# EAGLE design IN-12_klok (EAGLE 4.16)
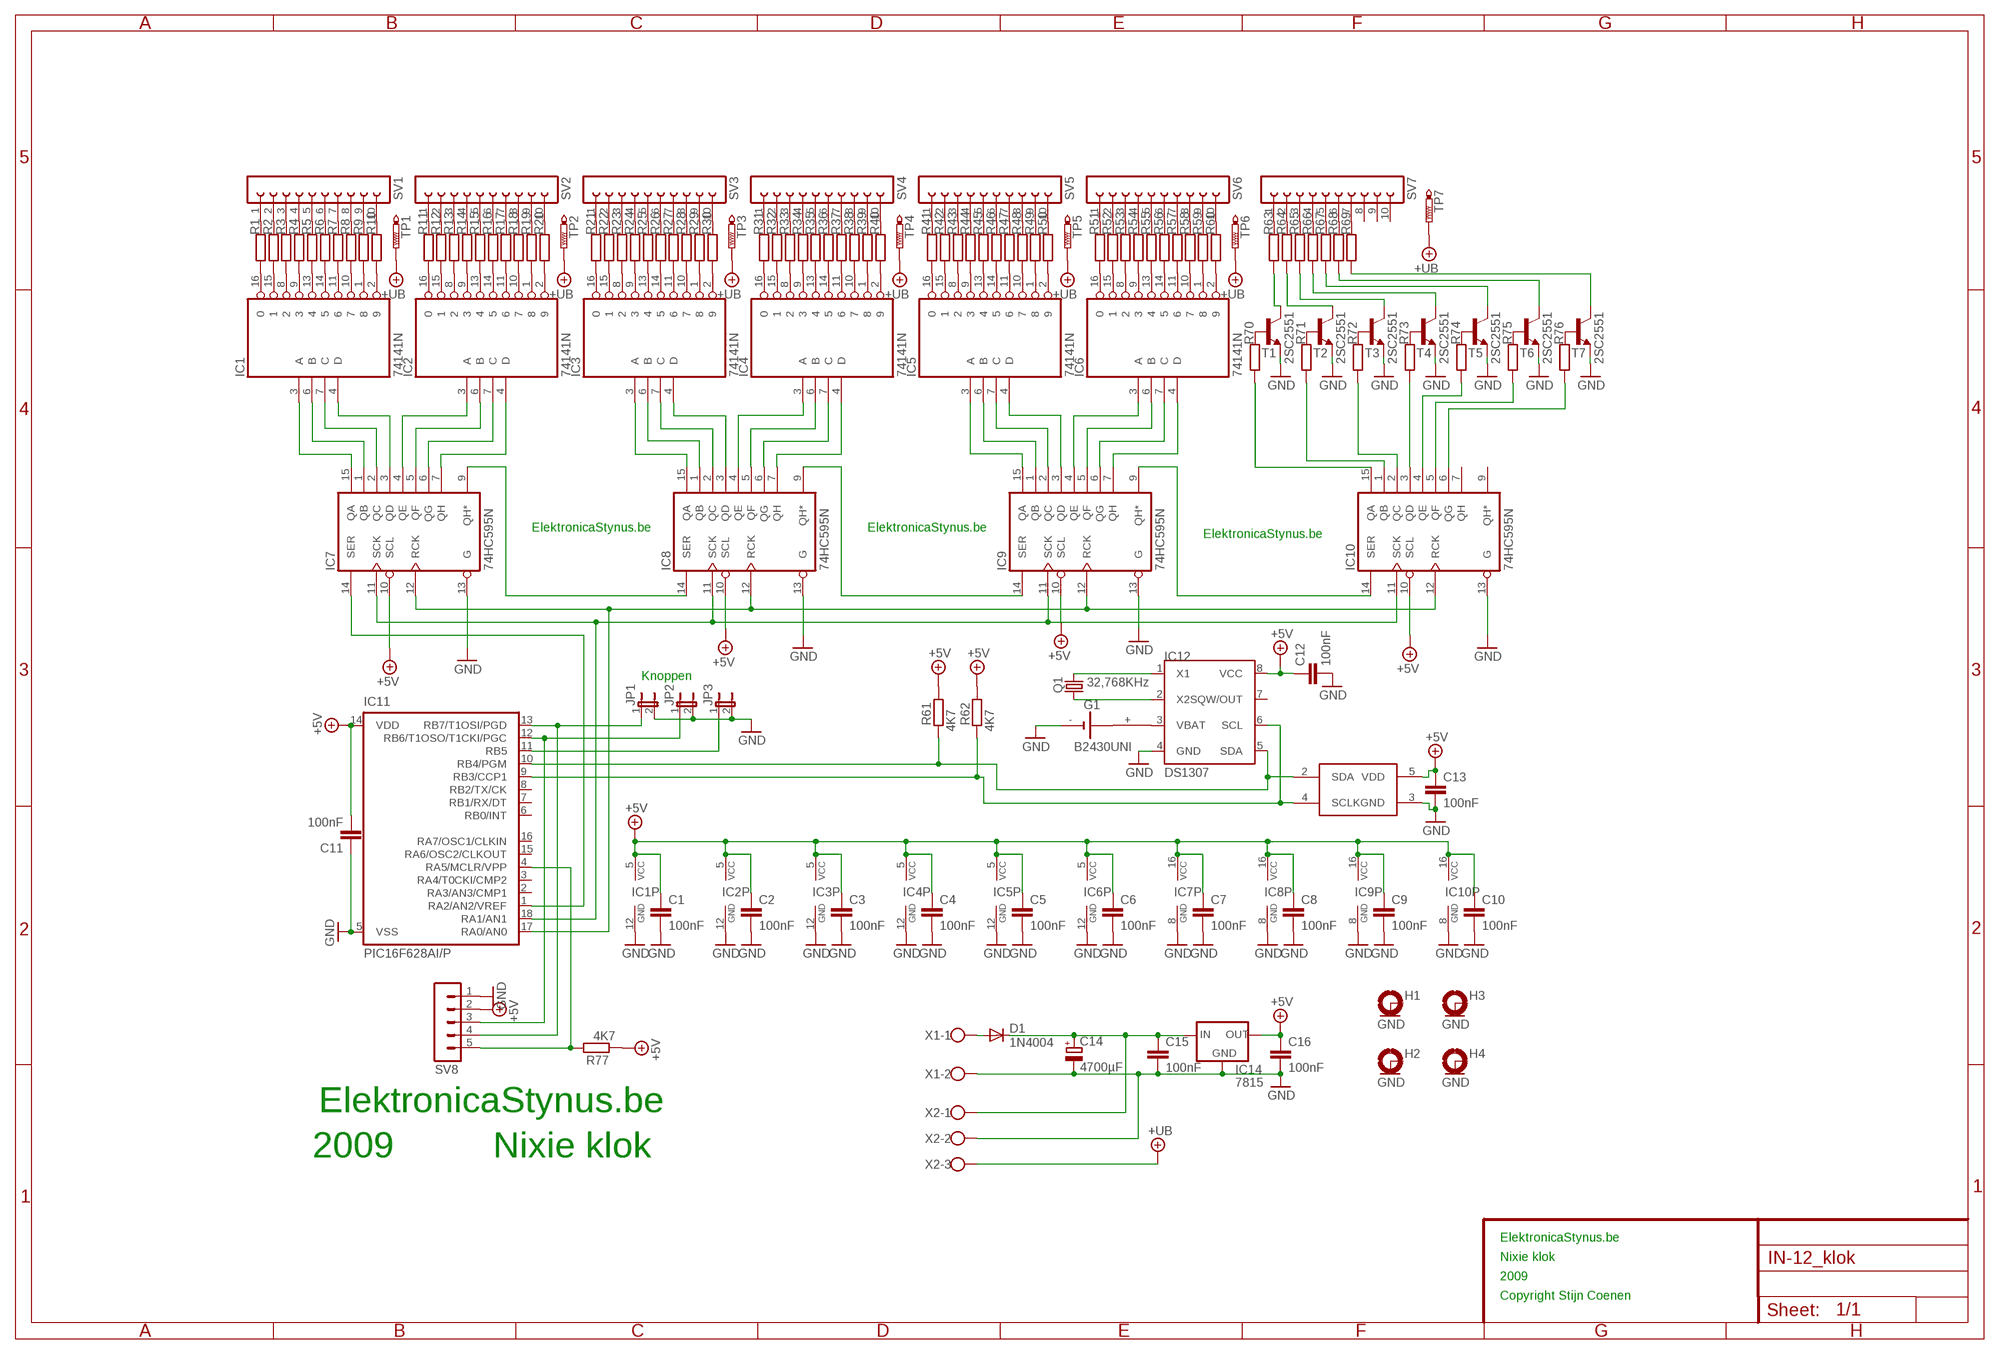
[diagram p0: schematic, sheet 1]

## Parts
C1  100nF  C-EU050-025X075  [C050-025X075]
C2  100nF  C-EU050-025X075  [C050-025X075]
C3  100nF  C-EU050-025X075  [C050-025X075]
C4  100nF  C-EU050-025X075  [C050-025X075]
C5  100nF  C-EU050-025X075  [C050-025X075]
C6  100nF  C-EU050-025X075  [C050-025X075]
C7  100nF  C-EU050-025X075  [C050-025X075]
C8  100nF  C-EU050-025X075  [C050-025X075]
C9  100nF  C-EU050-025X075  [C050-025X075]
C10  100nF  C-EU050-025X075  [C050-025X075]
C11  100nF  C-EU050-025X075  [C050-025X075]
C12  100nF  C-EU050-025X075  [C050-025X075]
C13  100nF  C-EU050-025X075  [C050-025X075]
C14  4700µF  CPOL-EUE7.5-18  [E7,5-18]
C15  100nF  C-EU050-025X075  [C050-025X075]
C16  100nF  C-EU050-025X075  [C050-025X075]
D1  1N4004  [DO41-10]
G1  B2430UNI  [B2430UNI]
H1  MOUNT-PAD-ROUND3.0  [3,0-PAD]
H2  MOUNT-PAD-ROUND3.0  [3,0-PAD]
H3  MOUNT-PAD-ROUND3.0  [3,0-PAD]
H4  MOUNT-PAD-ROUND3.0  [3,0-PAD]
IC1  74141N  [DIL16]
IC2  74141N  [DIL16]
IC3  74141N  [DIL16]
IC4  74141N  [DIL16]
IC5  74141N  [DIL16]
IC6  74141N  [DIL16]
IC7  74HC595N  [DIL16]
IC8  74HC595N  [DIL16]
IC9  74HC595N  [DIL16]
IC10  74HC595N  [DIL16]
IC11  PIC16F628AI/P  [DIL18]
IC12  DS1307  [DIL8]
IC13  TC74  [CB360]
IC14  7815  78XXS  [78XXS]
JP1  JP1E  [JP1]
JP2  JP1E  [JP1]
JP3  JP1E  [JP1]
Q1  32,768KHz  CRYSTALTC38H  [TC38H]
R1  R-EU_0204/7  [0204/7]
R2  R-EU_0204/7  [0204/7]
R3  R-EU_0204/7  [0204/7]
R4  R-EU_0204/7  [0204/7]
R5  R-EU_0204/7  [0204/7]
R6  R-EU_0204/7  [0204/7]
R7  R-EU_0204/7  [0204/7]
R8  R-EU_0204/7  [0204/7]
R9  R-EU_0204/7  [0204/7]
R10  R-EU_0204/7  [0204/7]
R11  R-EU_0204/7  [0204/7]
R12  R-EU_0204/7  [0204/7]
R13  R-EU_0204/7  [0204/7]
R14  R-EU_0204/7  [0204/7]
R15  R-EU_0204/7  [0204/7]
R16  R-EU_0204/7  [0204/7]
R17  R-EU_0204/7  [0204/7]
R18  R-EU_0204/7  [0204/7]
R19  R-EU_0204/7  [0204/7]
R20  R-EU_0204/7  [0204/7]
R21  R-EU_0204/7  [0204/7]
R22  R-EU_0204/7  [0204/7]
R23  R-EU_0204/7  [0204/7]
R24  R-EU_0204/7  [0204/7]
R25  R-EU_0204/7  [0204/7]
R26  R-EU_0204/7  [0204/7]
R27  R-EU_0204/7  [0204/7]
R28  R-EU_0204/7  [0204/7]
R29  R-EU_0204/7  [0204/7]
R30  R-EU_0204/7  [0204/7]
R31  R-EU_0204/7  [0204/7]
R32  R-EU_0204/7  [0204/7]
R33  R-EU_0204/7  [0204/7]
R34  R-EU_0204/7  [0204/7]
R35  R-EU_0204/7  [0204/7]
R36  R-EU_0204/7  [0204/7]
R37  R-EU_0204/7  [0204/7]
R38  R-EU_0204/7  [0204/7]
R39  R-EU_0204/7  [0204/7]
R40  R-EU_0204/7  [0204/7]
R41  R-EU_0204/7  [0204/7]
R42  R-EU_0204/7  [0204/7]
R43  R-EU_0204/7  [0204/7]
R44  R-EU_0204/7  [0204/7]
R45  R-EU_0204/7  [0204/7]
R46  R-EU_0204/7  [0204/7]
R47  R-EU_0204/7  [0204/7]
R48  R-EU_0204/7  [0204/7]
R49  R-EU_0204/7  [0204/7]
R50  R-EU_0204/7  [0204/7]
R51  R-EU_0204/7  [0204/7]
R52  R-EU_0204/7  [0204/7]
R53  R-EU_0204/7  [0204/7]
R54  R-EU_0204/7  [0204/7]
R55  R-EU_0204/7  [0204/7]
R56  R-EU_0204/7  [0204/7]
R57  R-EU_0204/7  [0204/7]
R58  R-EU_0204/7  [0204/7]
R59  R-EU_0204/7  [0204/7]
R60  R-EU_0204/7  [0204/7]
R61  4K7  R-EU_0204/7  [0204/7]
R62  4K7  R-EU_0204/7  [0204/7]
R63  R-EU_0204/7  [0204/7]
R64  R-EU_0204/7  [0204/7]
R65  R-EU_0204/7  [0204/7]
R66  R-EU_0204/7  [0204/7]
R67  R-EU_0204/7  [0204/7]
R68  R-EU_0204/7  [0204/7]
R69  R-EU_0204/7  [0204/7]
R70  R-EU_0204/7  [0204/7]
R71  R-EU_0204/7  [0204/7]
R72  R-EU_0204/7  [0204/7]
R73  R-EU_0204/7  [0204/7]
R74  R-EU_0204/7  [0204/7]
R75  R-EU_0204/7  [0204/7]
R76  R-EU_0204/7  [0204/7]
R77  4K7  R-EU_0204/7  [0204/7]
SV1  FE10-1  [FE10]
SV2  FE10-1  [FE10]
SV3  FE10-1  [FE10]
SV4  FE10-1  [FE10]
SV5  FE10-1  [FE10]
SV6  FE10-1  [FE10]
SV7  FE10-1  [FE10]
SV8  MA05-1  [MA05-1]
T1  2SC2551  [TO92-BCE]
T2  2SC2551  [TO92-BCE]
T3  2SC2551  [TO92-BCE]
T4  2SC2551  [TO92-BCE]
T5  2SC2551  [TO92-BCE]
T6  2SC2551  [TO92-BCE]
T7  2SC2551  [TO92-BCE]
TP1  PTR1PAD1-13Y  [P1-13Y]
TP2  PTR1PAD1-13Y  [P1-13Y]
TP3  PTR1PAD1-13Y  [P1-13Y]
TP4  PTR1PAD1-13Y  [P1-13Y]
TP5  PTR1PAD1-13Y  [P1-13Y]
TP6  PTR1PAD1-13Y  [P1-13Y]
TP7  PTR1PAD1-13Y  [P1-13Y]
X1  W237-02P  [W237-132]
X2  W237-3E  [W237-3E]

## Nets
+5V: C1.1 C2.1 C3.1 C4.1 C5.1 C6.1 C7.1 C8.1 C9.1 C10.1 C11.2 C12.1 C13.1 C16.1 IC1.5(VCC) IC2.5(VCC) IC3.5(VCC) IC4.5(VCC) IC5.5(VCC) IC6.5(VCC) IC7.10(SCL) IC7.16(VCC) IC8.10(SCL) IC8.16(VCC) IC9.10(SCL) IC9.16(VCC) IC10.10(SCL) IC10.16(VCC) IC11.14(VDD) IC12.8(VCC) IC13.5(VDD) IC14.OUT R61.2 R62.2 R77.1 SV8.2
+UB: TP1.1(TP) TP2.1(TP) TP3.1(TP) TP4.1(TP) TP5.1(TP) TP6.1(TP) TP7.1(TP) X2.3
GND: C1.2 C2.2 C3.2 C4.2 C5.2 C6.2 C7.2 C8.2 C9.2 C10.2 C11.1 C12.2 C13.2 C14.- C15.2 C16.2 G1.- H1.B3,0(MOUNT) H2.B3,0(MOUNT) H3.B3,0(MOUNT) H4.B3,0(MOUNT) IC1.12(GND) IC2.12(GND) IC3.12(GND) IC4.12(GND) IC5.12(GND) IC6.12(GND) IC7.8(GND) IC7.13(G) IC8.8(GND) IC8.13(G) IC9.8(GND) IC9.13(G) IC10.8(GND) IC10.13(G) IC11.5(VSS) IC12.4(GND) IC13.3(GND) IC14.GND JP1.2 JP2.2 JP3.2 SV8.1 T1.E T2.E T3.E T4.E T5.E T6.E T7.E X1.2 X2.2
N$1: IC1.3(A) IC7.15(QA)
N$2: IC1.6(B) IC7.1(QB)
N$3: IC1.7(C) IC7.2(QC)
N$4: IC1.4(D) IC7.3(QD)
N$5: IC2.3(A) IC7.4(QE)
N$6: IC2.6(B) IC7.5(QF)
N$7: IC2.7(C) IC7.6(QG)
N$8: IC2.4(D) IC7.7(QH)
N$9: IC3.4(D) IC8.3(QD)
N$10: IC3.7(C) IC8.2(QC)
N$11: IC3.6(B) IC8.1(QB)
N$12: IC3.3(A) IC8.15(QA)
N$13: IC4.3(A) IC8.4(QE)
N$14: IC4.6(B) IC8.5(QF)
N$15: IC4.7(C) IC8.6(QG)
N$16: IC4.4(D) IC8.7(QH)
N$17: IC5.4(D) IC9.3(QD)
N$18: IC5.7(C) IC9.2(QC)
N$19: IC5.6(B) IC9.1(QB)
N$20: IC5.3(A) IC9.15(QA)
N$21: IC6.3(A) IC9.4(QE)
N$22: IC6.6(B) IC9.5(QF)
N$23: IC6.7(C) IC9.6(QG)
N$24: IC6.4(D) IC9.7(QH)
N$25: IC7.11(SCK) IC8.11(SCK) IC9.11(SCK) IC10.11(SCK) IC11.18(RA1/AN1)
N$26: IC7.12(RCK) IC8.12(RCK) IC9.12(RCK) IC10.12(RCK) IC11.17(RA0/AN0)
N$27: IC7.14(SER) IC11.1(RA2/AN2/VREF)
N$28: IC7.9(QH*) IC8.14(SER)
N$29: IC8.9(QH*) IC9.14(SER)
N$30: IC9.9(QH*) IC10.14(SER)
N$31: IC1.16 R1.1
N$32: IC1.15 R2.1
N$33: IC1.8 R3.1
N$34: IC1.9 R4.1
N$35: IC1.13 R5.1
N$36: IC1.14 R6.1
N$37: IC1.11 R7.1
N$38: IC1.10 R8.1
N$39: IC1.1 R9.1
N$40: IC1.2 R10.1
N$41: IC2.16 R11.1
N$42: IC2.15 R12.1
N$43: IC2.8 R13.1
N$44: IC2.9 R14.1
N$45: IC2.13 R15.1
N$46: IC2.14 R16.1
N$47: IC2.11 R17.1
N$48: IC2.10 R18.1
N$49: IC2.1 R19.1
N$50: IC2.2 R20.1
N$51: IC3.16 R21.1
N$52: IC3.15 R22.1
N$53: IC3.8 R23.1
N$54: IC3.9 R24.1
N$55: IC3.13 R25.1
N$56: IC3.14 R26.1
N$57: IC3.11 R27.1
N$58: IC3.10 R28.1
N$59: IC3.1 R29.1
N$60: IC3.2 R30.1
N$61: IC4.16 R31.1
N$62: IC4.15 R32.1
N$63: IC4.8 R33.1
N$64: IC4.9 R34.1
N$65: IC4.13 R35.1
N$66: IC4.14 R36.1
N$67: IC4.11 R37.1
N$68: IC4.10 R38.1
N$69: IC4.1 R39.1
N$70: IC4.2 R40.1
N$71: IC5.16 R41.1
N$72: IC5.15 R42.1
N$73: IC5.8 R43.1
N$74: IC5.9 R44.1
N$75: IC5.13 R45.1
N$76: IC5.14 R46.1
N$77: IC5.11 R47.1
N$78: IC5.10 R48.1
N$79: IC5.1 R49.1
N$80: IC5.2 R50.1
N$81: IC6.16 R51.1
N$82: IC6.15 R52.1
N$83: IC6.8 R53.1
N$84: IC6.9 R54.1
N$85: IC6.13 R55.1
N$86: IC6.14 R56.1
N$87: IC6.11 R57.1
N$88: IC6.10 R58.1
N$89: IC6.1 R59.1
N$90: IC6.2 R60.1
N$91: R1.2 SV1.1
N$92: R2.2 SV1.2
N$93: R3.2 SV1.3
N$94: R4.2 SV1.4
N$95: R5.2 SV1.5
N$96: R6.2 SV1.6
N$97: R7.2 SV1.7
N$98: R8.2 SV1.8
N$99: R9.2 SV1.9
N$100: R10.2 SV1.10
N$101: R11.2 SV2.1
N$102: R12.2 SV2.2
N$103: R13.2 SV2.3
N$104: R14.2 SV2.4
N$105: R15.2 SV2.5
N$106: R16.2 SV2.6
N$107: R17.2 SV2.7
N$108: R18.2 SV2.8
N$109: R19.2 SV2.9
N$110: R20.2 SV2.10
N$111: R21.2 SV3.1
N$112: R22.2 SV3.2
N$113: R23.2 SV3.3
N$114: R24.2 SV3.4
N$115: R25.2 SV3.5
N$116: R26.2 SV3.6
N$117: R27.2 SV3.7
N$118: R28.2 SV3.8
N$119: R29.2 SV3.9
N$120: R30.2 SV3.10
N$121: R31.2 SV4.1
N$122: R32.2 SV4.2
N$123: R33.2 SV4.3
N$124: R34.2 SV4.4
N$125: R35.2 SV4.5
N$126: R36.2 SV4.6
N$127: R37.2 SV4.7
N$128: R38.2 SV4.8
N$129: R39.2 SV4.9
N$130: R40.2 SV4.10
N$131: R41.2 SV5.1
N$132: R42.2 SV5.2
N$133: R43.2 SV5.3
N$134: R44.2 SV5.4
N$135: R45.2 SV5.5
N$136: R46.2 SV5.6
N$137: R47.2 SV5.7
N$138: R48.2 SV5.8
N$139: R49.2 SV5.9
N$140: R50.2 SV5.10
N$141: R51.2 SV6.1
N$142: R52.2 SV6.2
N$143: R53.2 SV6.3
N$144: R54.2 SV6.4
N$145: R55.2 SV6.5
N$146: R56.2 SV6.6
N$147: R57.2 SV6.7
N$148: R58.2 SV6.8
N$149: R59.2 SV6.9
N$150: R60.2 SV6.10
N$151: IC12.1(X1) Q1.2
N$152: IC12.2(X2) Q1.1
N$153: G1.+ IC12.3(VBAT)
N$154: IC11.10(RB4/PGM) IC12.5(SDA) IC13.2(SDA) R61.1
N$155: IC11.9(RB3/CCP1) IC12.6(SCL) IC13.4(SCLK) R62.1
N$156: R63.2 SV7.1
N$157: R64.2 SV7.2
N$158: R65.2 SV7.3
N$159: R66.2 SV7.4
N$160: R67.2 SV7.5
N$161: R68.2 SV7.6
N$162: R69.2 SV7.7
N$163: D1.A X1.1
N$164: C14.+ C15.1 D1.C IC14.IN X2.1
N$165: IC11.11(RB5) JP3.1
N$166: IC11.12(RB6/T1OSO/T1CKI/PGC) JP2.1 SV8.3
N$167: IC11.13(RB7/T1OSI/PGD) JP1.1 SV8.4
N$168: R70.2 T1.B
N$169: R71.2 T2.B
N$170: R72.2 T3.B
N$171: R73.2 T4.B
N$172: R74.2 T5.B
N$173: R75.2 T6.B
N$174: R76.2 T7.B
N$175: R63.1 T1.C
N$176: R64.1 T2.C
N$177: R65.1 T3.C
N$178: R66.1 T4.C
N$179: R67.1 T5.C
N$180: R68.1 T6.C
N$181: R69.1 T7.C
N$182: IC10.15(QA) R70.1
N$183: IC10.1(QB) R71.1
N$184: IC10.2(QC) R72.1
N$185: IC10.3(QD) R73.1
N$186: IC10.4(QE) R74.1
N$187: IC10.5(QF) R75.1
N$188: IC10.6(QG) R76.1
N$189: IC11.4(RA5/MCLR/VPP) R77.2 SV8.5
Unconnected: G1.+@1(+) G1.+@2(+) G1.+@3(+) G1.+@4(+) G1.-@1(-) IC10.7(QH) IC10.9(QH*) IC11.2(RA3/AN3/CMP1) IC11.3(RA4/T0CKI/CMP2) IC11.6(RB0/INT) IC11.7(RB1/RX/DT) IC11.8(RB2/TX/CK) IC11.15(RA6/OSC2/CLKOUT) IC11.16(RA7/OSC1/CLKIN) IC12.7(SQW/OUT) SV7.8 SV7.9 SV7.10

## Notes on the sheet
- ElektronicaStynus.be | ElektronicaStynus.be
- ElektronicaStynus.be
- Knoppen
- ElektronicaStynus.be
- 2009 | Nixie klok
- ElektronicaStynus.be
- Nixie klok
- 2009
- Copyright Stijn Coenen

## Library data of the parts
C1-C13 C15 C16 = rcl:C-EU: CAPACITOR, European symbol
C14 = rcl:CPOL-EU: POLARIZED CAPACITOR, European symbol
D1 = diode:1N4004: DIODE
G1 = battery:B2430UNI: LI BATTERY
H1-H4 = holes:MOUNT-PAD-ROUND: MOUNTING PAD, round
IC1-IC6 = 74xx-eu:74*141: BCD to decimal DECODER/DRIVER
IC7-IC10 = 74xx-eu:74*595: 8-bit SHIFT REGISTER, output latch
IC11 = microchip-4:PIC16F628*: MICROCONTROLLER PIC16F628(A) 16 I/O One 16-bit timer (TMR0) Two 8-bit timer (TMR0) Two comparators USART CCP/PWM Precision 4 MHz internal oscillator 2k Program Flash memory 224 bytes SRAM 128 bytes EEPROM
IC12 = dallas-1:DS1307: I2C Serial RTC w/56 bytes battery backed RAM
IC13 = TC74:TC74
IC14 = v-reg:78XXS: VOLTAGE REGULATOR
JP1-JP3 = jumper:JP1E: JUMPER
Q1 = crystal:CRYSTAL: CRYSTAL
R1-R77 = rcl:R-EU_: RESISTOR, European symbol
SV1-SV7 = con-lsta:FE10-1: FEMALE HEADER
SV8 = con-lstb:MA05-1: PIN HEADER
T1-T7 = transistor-npn:2SC2551
TP1-TP7 = testpad:PTR1: TEST PIN
X1 = con-wago-508:W237-02P: WAGO SREW CLAMP
X2 = con-wago-508:W237-3E: WAGO SREW CLAMP

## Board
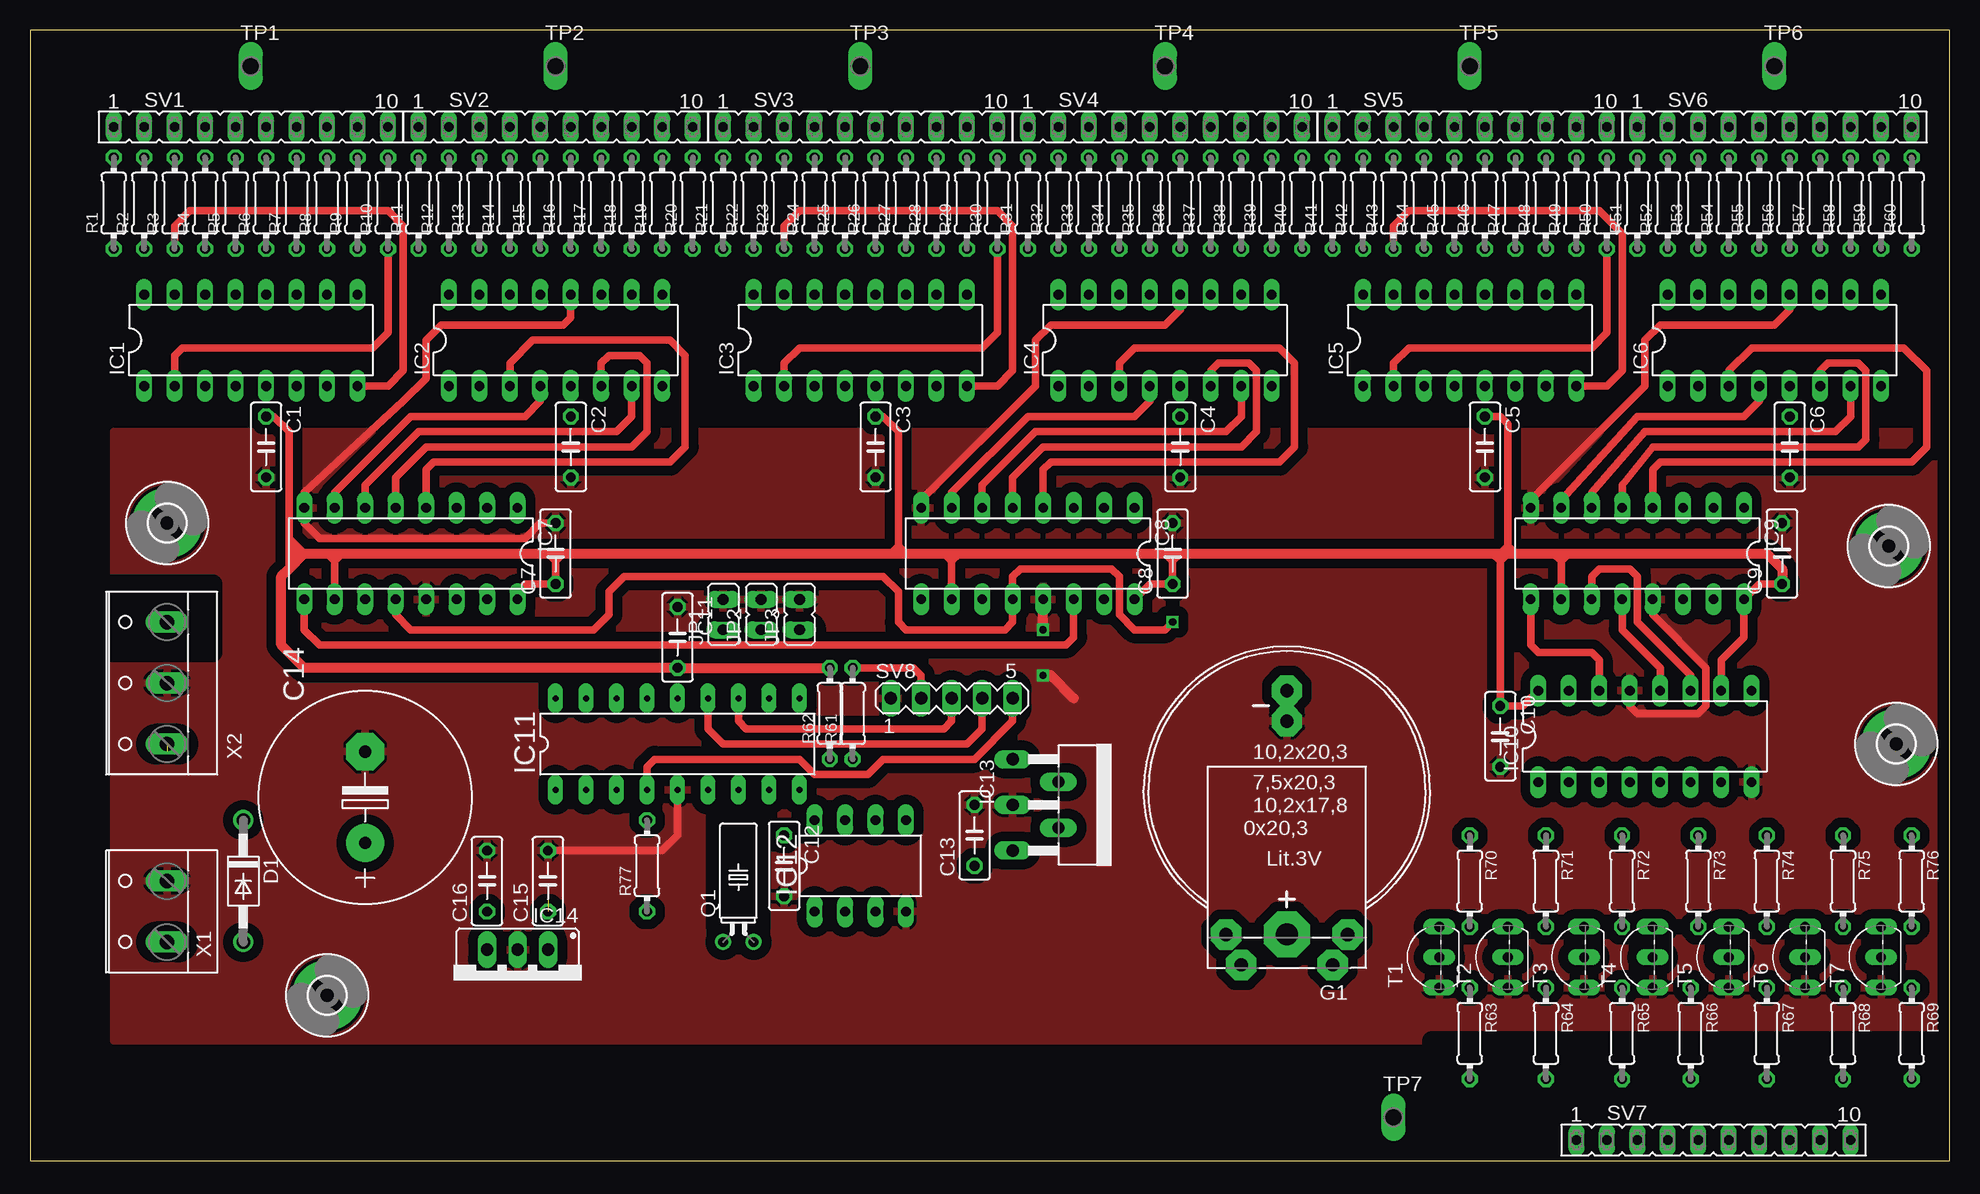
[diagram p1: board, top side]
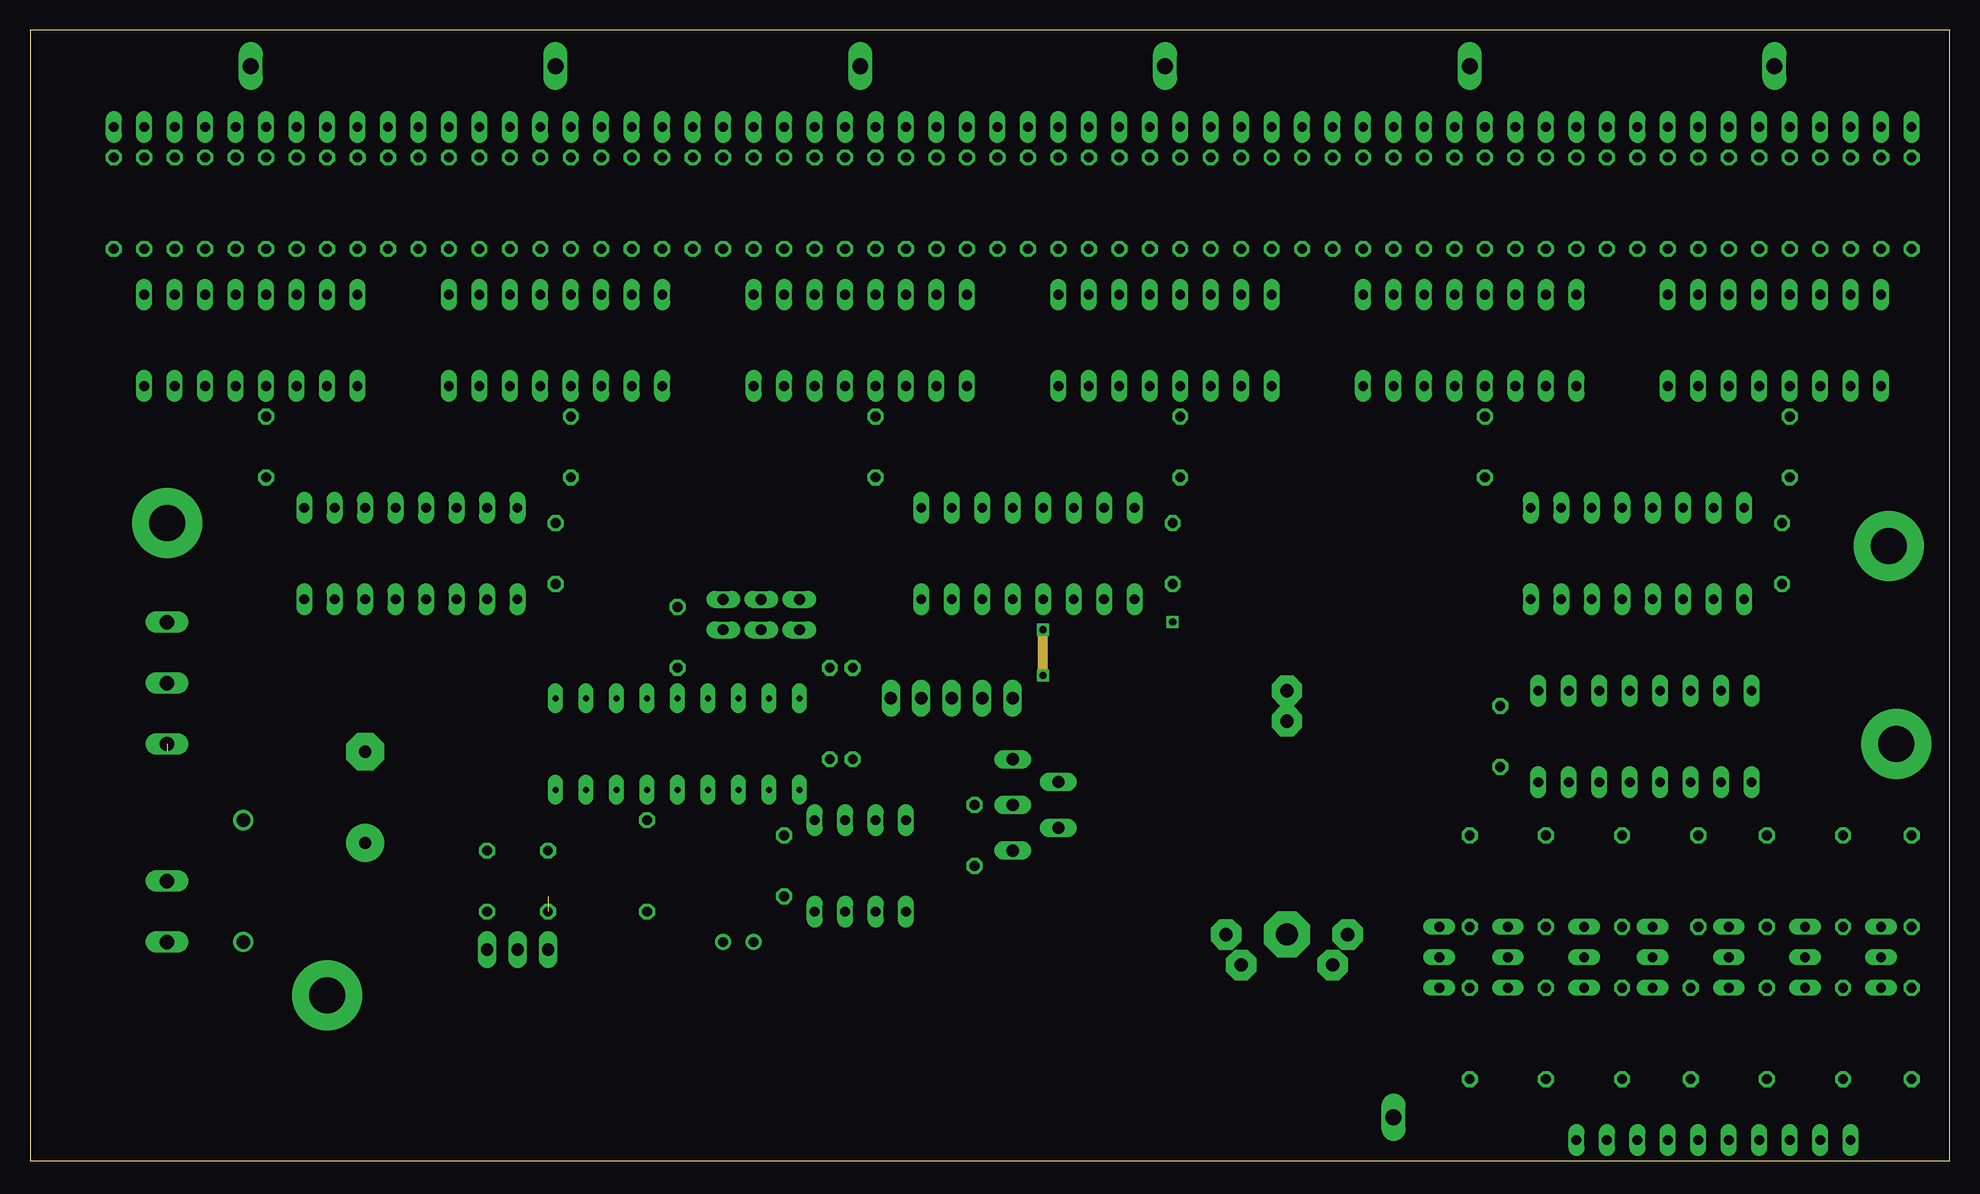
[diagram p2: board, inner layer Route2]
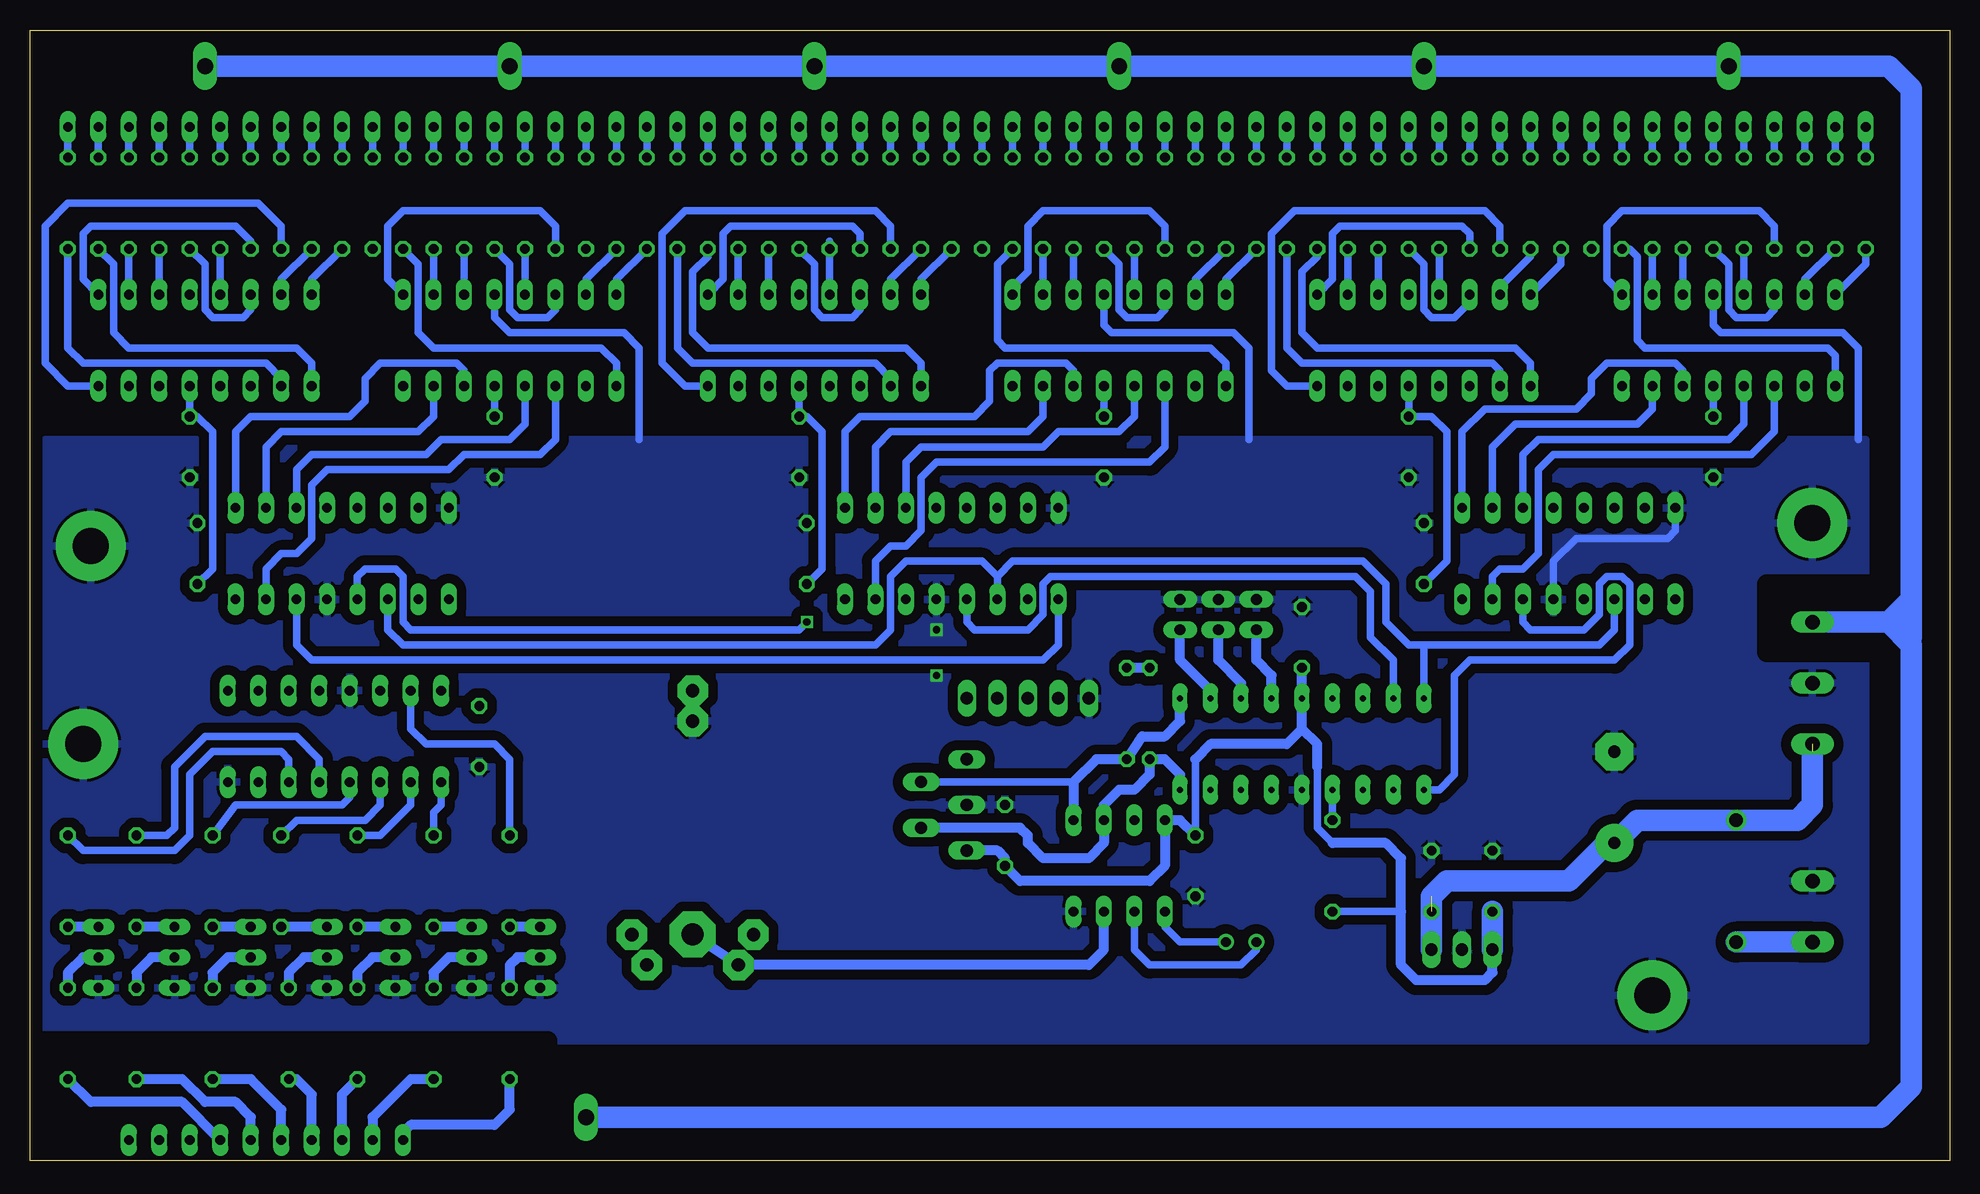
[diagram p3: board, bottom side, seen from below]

Size 160 x 94.28 mm. Coordinates in mm from the lower left corner, seen from the top.
Outline: 0,0 160,0 160,94.28 0,94.28 0,0
Copper layers (1*16): Top 0.035mm / dielectric 1.5mm / Bottom 0.035mm
Design rules "default": minimum track width 10mil, minimum drill 24mil, track to track 8mil, track to pad 8mil, pad to pad 8mil, via to via 8mil, smd to smd 8mil, copper to edge 40mil, drill to drill 8mil, minimum pad ring 10mil, minimum via ring 8mil, stop-mask expansion 4mil, vias tented up to drill 0mil, thermal gap 10mil
tRestrict: area 5.7,42.4 to 15.2,48.1; area 116.8,0.5 to 158.7,10; area 57.1,19.5 to 61,28.4
bRestrict: area 5.7,42.4 to 15.2,48.1; area 116.8,0.5 to 158.7,10

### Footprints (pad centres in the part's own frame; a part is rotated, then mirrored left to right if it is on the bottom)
C050-025X075 = drill 0.813 octagon: 1 -2.54,0; 2 2.54,0
E7,5-18 = drill 1.016 pad 3.15 round: + -3.81,0 | drill 1.016 pad 3.15 octagon: - 3.81,0
DO41-10 = drill 1.118 round: A 5.08,0; C -5.08,0
B2430UNI = drill 1.118 pad 2.54 octagon: + 3.81,14.605; +@1 -3.81,14.605; +@2 -5.08,12.065; +@3 5.08,12.065; - 0,-5.715; -@1 0,-8.255 | drill 1.803 pad 3.81 octagon: +@4 0,12.065
3,0-PAD = drill 3 pad 5.842 round: B3,0 0,0
DIL16 = drill 0.813 long: 1 -8.89,-3.81; 2 -6.35,-3.81; 3 -3.81,-3.81; 4 -1.27,-3.81; 5 1.27,-3.81; 6 3.81,-3.81; 7 6.35,-3.81; 8 8.89,-3.81; 9 8.89,3.81; 10 6.35,3.81; 11 3.81,3.81; 12 1.27,3.81; 13 -1.27,3.81; 14 -3.81,3.81; 15 -6.35,3.81; 16 -8.89,3.81
DIL18 = drill 0.5 pad 1.27 long: 1 -10.16,-3.81; 2 -7.62,-3.81; 3 -5.08,-3.81; 4 -2.54,-3.81; 5 0,-3.81; 6 2.54,-3.81; 7 5.08,-3.81; 8 7.62,-3.81; 9 10.16,-3.81; 10 10.16,3.81; 11 7.62,3.81; 12 5.08,3.81; 13 2.54,3.81; 14 0,3.81; 15 -2.54,3.81; 16 -5.08,3.81; 17 -7.62,3.81; 18 -10.16,3.81
DIL8 = drill 0.813 long: 1 -3.81,-3.81; 2 -1.27,-3.81; 3 1.27,-3.81; 4 3.81,-3.81; 5 3.81,3.81; 6 1.27,3.81; 7 -1.27,3.81; 8 -3.81,3.81
CB360 = drill 1.016 long: 1 -3.81,-8.255; 2 -1.905,-4.445; 3 0,-8.255; 4 1.905,-4.445; 5 3.81,-8.255
78XXS = drill 1.016 long: GND 0,-2.54; IN -2.54,-2.54; OUT 2.54,-2.54
JP1 = drill 0.914 long: 1 0,-1.27; 2 0,1.27
TC38H = drill 0.813 round: 1 -1.27,0; 2 1.27,0
0204/7 = drill 0.813 octagon: 1 -3.81,0; 2 3.81,0
FE10 = drill 0.813 long: 1 -11.43,0; 2 -8.89,0; 3 -6.35,0; 4 -3.81,0; 5 -1.27,0; 6 1.27,0; 7 3.81,0; 8 6.35,0; 9 8.89,0; 10 11.43,0
MA05-1 = drill 1.016 long: 1 -5.08,0; 2 -2.54,0; 3 0,0; 4 2.54,0; 5 5.08,0
TO92-BCE = drill 0.813 long: B 2.54,0; C 0,0; E -2.54,0
P1-13Y = drill 1.321 pad 1.905 long: 1 0,0
W237-132 = drill 1.194 long: 1 -2.54,-0.635; 2 2.54,-0.635
W237-3E = drill 1.194 long: 1 -5.08,-0.635; 2 0,-0.635; 3 5.08,-0.635

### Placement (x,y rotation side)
C1  19.68,59.52 270 top
C2  45.08,59.52 270 top
C3  70.48,59.52 270 top
C4  95.88,59.52 270 top
C5  121.28,59.52 270 top
C6  146.68,59.52 270 top
C7  43.81,50.64 90 top
C8  95.24,50.64 90 top
C9  146.04,50.64 90 top
C10  122.55,35.4 270 top
C11  53.97,43.65 270 top
C12  62.86,24.6 270 top
C13  78.73,27.14 90 top
C14  27.93,30.32 90 top
C15  43.18,23.33 90 top
C16  38.1,23.33 90 top
D1  17.77,23.33 270 top
G1  104.77,30.95 180 top
H1  11.43,53.18 0 top
H2  154.94,51.27 0 top
H3  24.76,13.8 0 top
H4  155.57,34.76 0 top
IC1  18.41,68.41 0 top
IC2  43.81,68.41 0 top
IC3  69.21,68.41 0 top
IC4  94.61,68.41 0 top
IC5  120.01,68.41 0 top
IC6  145.41,68.41 0 top
IC7  31.74,50.64 180 top
IC8  83.18,50.64 180 top
IC9  133.98,50.64 180 top
IC10  134.62,35.4 0 top
IC11  53.97,34.76 0 top
IC12  69.21,24.6 0 top
IC13  90.16,29.68 270 top
IC14  40.64,15.07 180 top
JP1  57.78,45.55 0 top
JP2  60.96,45.55 0 top
JP3  64.13,45.55 0 top
Q1  59.05,18.25 0 top
R1  6.98,79.84 90 top
R2  9.52,79.84 90 top
R3  12.06,79.84 90 top
R4  14.6,79.84 90 top
R5  17.14,79.84 90 top
R6  19.68,79.84 90 top
R7  22.22,79.84 90 top
R8  24.76,79.84 90 top
R9  27.3,79.84 90 top
R10  29.84,79.84 90 top
R11  32.38,79.84 90 top
R12  34.92,79.84 90 top
R13  37.46,79.84 90 top
R14  40,79.84 90 top
R15  42.54,79.84 90 top
R16  45.08,79.84 90 top
R17  47.62,79.84 90 top
R18  50.16,79.84 90 top
R19  52.7,79.84 90 top
R20  55.24,79.84 90 top
R21  57.78,79.84 90 top
R22  60.32,79.84 90 top
R23  62.86,79.84 90 top
R24  65.4,79.84 90 top
R25  67.94,79.84 90 top
R26  70.48,79.84 90 top
R27  73.02,79.84 90 top
R28  75.56,79.84 90 top
R29  78.1,79.84 90 top
R30  80.64,79.84 90 top
R31  83.18,79.84 90 top
R32  85.72,79.84 90 top
R33  88.26,79.84 90 top
R34  90.8,79.84 90 top
R35  93.34,79.84 90 top
R36  95.88,79.84 90 top
R37  98.42,79.84 90 top
R38  100.96,79.84 90 top
R39  103.5,79.84 90 top
R40  106.04,79.84 90 top
R41  108.58,79.84 90 top
R42  111.12,79.84 90 top
R43  113.66,79.84 90 top
R44  116.2,79.84 90 top
R45  118.74,79.84 90 top
R46  121.28,79.84 90 top
R47  123.82,79.84 90 top
R48  126.36,79.84 90 top
R49  128.9,79.84 90 top
R50  131.44,79.84 90 top
R51  133.98,79.84 90 top
R52  136.52,79.84 90 top
R53  139.06,79.84 90 top
R54  141.6,79.84 90 top
R55  144.14,79.84 90 top
R56  146.68,79.84 90 top
R57  149.22,79.84 90 top
R58  151.76,79.84 90 top
R59  154.3,79.84 90 top
R60  156.84,79.84 90 top
R61  68.57,37.3 90 top
R62  66.67,37.3 90 top
R63  120.01,10.63 270 top
R64  126.36,10.63 270 top
R65  132.71,10.63 270 top
R66  138.42,10.63 270 top
R67  144.78,10.63 270 top
R68  151.12,10.63 270 top
R69  156.84,10.63 270 top
R70  120.01,23.33 270 top
R71  126.36,23.33 270 top
R72  132.71,23.33 270 top
R73  139.06,23.33 270 top
R74  144.78,23.33 270 top
R75  151.12,23.33 270 top
R76  156.84,23.33 270 top
R77  51.43,24.6 90 top
SV1  18.41,86.19 0 top
SV2  43.81,86.19 0 top
SV3  69.21,86.19 0 top
SV4  94.61,86.19 0 top
SV5  120.01,86.19 0 top
SV6  145.41,86.19 0 top
SV7  140.33,1.74 0 top
SV8  76.83,38.57 0 top
T1  117.47,16.98 90 top
T2  123.19,16.98 90 top
T3  129.53,16.98 90 top
T4  135.25,16.98 90 top
T5  141.6,16.98 90 top
T6  147.95,16.98 90 top
T7  154.3,16.98 90 top
TP1  18.41,91.27 0 top
TP2  43.81,91.27 0 top
TP3  69.21,91.27 0 top
TP4  94.61,91.27 0 top
TP5  120.01,91.27 0 top
TP6  145.41,91.27 0 top
TP7  113.66,3.65 0 top
X1  10.79,20.79 90 top
X2  10.79,39.84 90 top

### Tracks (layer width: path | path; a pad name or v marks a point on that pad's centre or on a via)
+5V
  Top 0.61: C1.1 20.31,62.07 21.58,60.8 21.58,51.91 | 22.86,50.64 21.58,51.91 | 24.76,50.64 25.39,50 | 25.39,50 IC7.10 | 25.39,50 26.03,50.64 | 43.18,50.64 43.81,50 | IC7.16 40.64,47.46 41.27,48.1 C7.1 43.81,50 | C3.1 71.11,62.07 72.38,60.8 72.38,51.27 | 73.02,50.64 72.38,51.27 | 76.19,50.64 76.83,50 | 76.83,50 IC8.10 | 94.61,50.64 95.24,50 | 95.24,50 C8.1 93.34,48.1 IC8.16 | 43.81,50 44.45,50.64 | 95.24,50 95.88,50.64 | 95.24,50 95.24,50.64 | 76.83,50 77.46,50.64 | 43.81,50 43.81,50.64 | 71.75,50.64 72.38,51.27 | C5.1 122.55,62.07 123.19,61.43 123.19,51.27 | 123.19,51.27 123.19,50.64 122.55,50 | 123.19,51.27 122.55,50.64 122.55,50 | 123.19,51.27 123.82,50.64 | 127.63,50.64 127.63,50 | 127.63,50 IC9.10 | C9.1 144.14,48.1 IC9.16 142.87,43.65 140.97,41.75 IC10.10 | 126.99,50.64 127.63,50 | 127.63,50 128.27,50.64 | 122.55,50 C10.1 124.45,37.94 IC10.16 | 21.58,51.27 21.58,51.91 | 21.58,51.27 21.58,49.37 21.58,50 22.22,50.64 21.58,51.27 | 121.91,50.64 122.55,50 | SV8.2 74.29,40.48 73.66,41.11 R61.2
  Top 0.813: C9.1 146.04,49.37 144.78,50.64 128.27,50.64 127.63,50.64 126.99,50.64 123.82,50.64 123.19,50.64 122.55,50.64 121.91,50.64 95.88,50.64 95.24,50.64 94.61,50.64 77.46,50.64 76.19,50.64 73.02,50.64 71.75,50.64 44.45,50.64 43.81,50.64 43.18,50.64 26.03,50.64 24.76,50.64 22.86,50.64 21.58,49.37 20.95,48.73 20.95,43.02 22.86,41.11 C11.2 R62.2
  Bottom 0.61: 62.86,33.49 C12.1 | C1.1 IC1.5 | IC2.5 C2.1 43.18,62.07 41.91,60.8 41.91,50 C7.1 | C3.1 IC3.5 | IC4.5 C4.1 95.24,62.07 93.97,60.8 93.97,49.37 C8.1 | C5.1 IC5.5 | IC6.5 C6.1 146.04,62.07 144.78,60.8 144.78,49.37 C9.1 | 52.7,32.86 52.7,27.78 51.43,26.5 | 45.72,20.79 R77.1
  Bottom 0.813: C12.1 64.13,28.41 IC12.8 65.4,24.6 66.67,23.33 77.46,23.33 C13.1 78.73,25.23 79.37,25.87 IC13.5 | R62.2 R61.2 | 62.86,33.49 61.59,34.76 55.24,34.76 53.97,36.03 | 53.97,36.03 IC11.14 C11.2 | 53.97,36.03 52.7,34.76 52.7,32.86 | 51.43,26.5 46.98,26.5 45.72,25.23 45.72,20.79 45.72,16.34 44.45,15.07 38.73,15.07 38.1,15.71 IC14.OUT
  Bottom 1.778: IC14.OUT C16.1
+UB
  Bottom 1.778: TP6.1 TP5.1 TP4.1 TP3.1 TP2.1 TP1.1 5.08,91.27 3.17,89.37 3.17,47.46 | 5.08,44.92 X2.3 | 5.08,44.92 3.17,46.83 3.17,47.46 | TP7.1 5.71,3.65 3.17,6.18 3.17,43.02 5.08,44.92 | 3.17,47.46 3.17,43.65
GND  (via drill 0.6)
  Top 0.61: IC2.12 45.08,70.32 44.45,69.69 34.29,69.69 33.02,68.41 33.02,65.24 31.11,63.34 22.86,55.72 IC7.8 22.86,53.18 24.12,51.91 41.27,51.91 42.54,53.18 C7.2 | IC4.12 95.88,70.95 94.61,69.69 85.08,69.69 83.81,68.41 83.81,64.6 74.29,55.08 IC8.8 | IC6.12 146.68,70.95 145.41,69.69 135.88,69.69 134.62,68.41 134.62,64.6 125.09,55.08 IC9.8 | IC11.5 53.97,30.32 53.97,27.14 52.7,25.87 C15.2 | IC9.13 135.25,45.55 139.69,41.11 139.69,37.94 139.06,37.3 133.98,37.3 133.34,37.94 IC10.13
  Top 0.813: v84.45,44.29 IC8.13 | v84.45,40.48 85.08,40.48 86.99,38.57
  Route2 0.813: v84.45,40.48 v84.45,44.29
  Bottom 0.61: IC1.12 19.68,69.69 19.04,69.05 8.89,69.05 7.62,67.78 7.62,60.16 | IC3.12 70.48,69.69 69.84,69.05 59.69,69.05 58.41,67.78 58.41,60.16 | IC5.12 121.28,70.32 120.01,69.05 110.48,69.05 109.21,67.78 109.21,60.16 | IC7.13 33.02,50 31.11,51.91 23.49,51.91 22.86,52.54 IC7.8
  pour Bottom (isolate 0.813): 6.98,60.16 158.75,60.16 158.75,10 6.98,10
  pour Top (isolate 0.813): 6.98,60.8 159.38,60.8 159.38,10 6.98,10
N$1
  Bottom 0.61: IC1.3 14.6,60.8 16.5,58.89 33.02,58.89 34.29,57.62 34.29,50.64 35.55,49.37 37.46,49.37 38.1,48.73 IC7.15
N$2
  Bottom 0.61: IC1.6 22.22,65.88 22.86,66.51 28.57,66.51 29.84,65.24 29.84,63.97 31.11,62.7 38.73,62.7 40.64,60.8 IC7.1
N$3
  Bottom 0.61: IC1.7 24.76,62.7 26.03,61.43 36.19,61.43 38.1,59.52 IC7.2
N$4
  Bottom 0.61: IC7.3 35.55,58.89 34.29,60.16 18.41,60.16 17.14,61.43 IC1.4
N$5
  Top 0.61: IC2.3 40,66.51 41.91,68.41 53.34,68.41 54.61,67.14 54.61,59.52 53.34,58.26 33.65,58.26 33.02,57.62 IC7.4
N$6
  Top 0.61: IC2.6 47.62,66.51 48.26,67.14 50.8,67.14 51.43,66.51 51.43,60.8 50.16,59.52 33.02,59.52 30.47,56.98 IC7.5
N$7
  Top 0.61: IC2.7 50.16,62.07 48.89,60.8 32.38,60.8 27.93,56.35 IC7.6
N$8
  Top 0.61: IC2.4 42.54,63.34 41.27,62.07 31.74,62.07 25.39,55.72 IC7.7
N$9
  Bottom 0.61: IC3.4 67.94,62.07 69.21,60.8 74.29,60.8 75.56,59.52 85.72,59.52 86.99,58.26 IC8.3
N$10
  Bottom 0.61: IC3.7 75.56,62.07 76.83,60.8 88.26,60.8 89.53,59.52 IC8.2
N$11
  Bottom 0.61: IC8.1 92.07,60.8 90.8,62.07 81.27,62.07 80,63.34 80,65.88 79.37,66.51 73.66,66.51 73.02,65.88 IC3.6
N$12
  Bottom 0.61: IC3.3 65.4,59.52 66.67,58.26 84.45,58.26 85.72,56.98 85.72,52.54 86.99,51.27 88.26,51.27 89.53,50 IC8.15
N$13
  Top 0.61: 84.45,55.08 IC8.4 84.45,57.62 85.08,58.26 104.13,58.26 105.41,59.52 105.41,66.51 104.13,67.78 92.07,67.78 90.8,66.51 IC4.3
N$14
  Top 0.61: IC4.6 98.42,65.88 99.05,66.51 101.59,66.51 102.23,65.88 102.23,60.8 100.96,59.52 84.45,59.52 81.91,56.98 IC8.5
N$15
  Top 0.61: IC8.6 79.37,56.35 83.81,60.8 99.69,60.8 100.96,62.07 IC4.7
N$16
  Top 0.61: IC4.4 93.34,63.34 92.07,62.07 83.18,62.07 76.83,55.72 IC8.7
N$17
  Bottom 0.61: IC5.4 118.74,61.43 120.01,60.16 125.72,60.16 126.99,58.89 136.52,58.89 137.79,57.62 IC9.3
N$18
  Bottom 0.61: IC5.7 126.36,62.07 127.63,60.8 139.06,60.8 140.33,59.52 IC9.2
N$19
  Bottom 0.61: IC5.6 123.82,65.88 124.45,66.51 130.81,66.51 132.07,65.24 132.07,63.34 133.34,62.07 141.6,62.07 142.87,60.8 IC9.1
N$20
  Bottom 0.61: IC5.3 116.2,60.16 117.47,58.89 123.82,58.89 125.09,57.62 135.25,57.62 136.52,56.35 136.52,51.91 137.79,50.64 139.06,50.64 140.33,49.37 IC9.15
N$21
  Top 0.61: IC6.3 141.6,65.88 143.5,67.78 156.2,67.78 158.11,65.88 158.11,59.52 156.84,58.26 135.88,58.26 135.25,57.62 IC9.4
N$22
  Top 0.61: IC9.5 132.71,56.35 135.25,59.52 152.39,59.52 153.03,60.16 153.03,65.88 152.39,66.51 149.85,66.51 149.22,65.88 IC6.6
N$23
  Top 0.61: IC9.6 130.17,55.72 134.62,60.8 150.49,60.8 151.76,62.07 IC6.7
N$24
  Top 0.61: IC6.4 144.14,63.34 142.87,62.07 133.98,62.07 127.63,55.08 IC9.7
N$25
  Top 0.61: IC10.11 138.42,40.48 133.98,44.92 133.98,48.73 133.34,49.37 130.81,49.37 130.17,48.73 IC9.11
  Bottom 0.61: 79.37,48.73 78.1,50 48.89,50 46.98,48.1 46.98,44.92 45.08,43.02 43.81,43.02 | 43.81,43.02 29.2,43.02 27.93,44.29 IC7.11 | 43.81,43.02 IC11.18 | 79.37,48.73 IC8.11 | 79.37,48.73 80.64,50 86.99,50 88.26,48.73 88.26,44.29 89.53,43.02 128.9,43.02 130.17,44.29 IC9.11
N$26  (via drill 0.6)
  Top 0.61: IC7.12 30.47,45.55 31.74,44.29 46.98,44.29 48.26,45.55 48.26,47.46 49.53,48.73 71.11,48.73 72.38,47.46 72.38,44.92 73.02,44.29 81.27,44.29 81.91,44.92 IC8.12 81.91,48.73 82.55,49.37 90.16,49.37 90.8,48.73 90.8,45.55 92.07,44.29 94.61,44.29 v95.24,44.92 | IC9.12 132.71,44.29 135.88,41.11 IC10.12
  Bottom 0.61: IC8.12 81.91,44.92 81.27,44.29 76.83,44.29 75.56,45.55 75.56,48.1 74.92,48.73 49.53,48.73 48.26,47.46 48.26,43.65 46.35,41.75 IC11.17 | v95.24,44.92 95.88,44.29 128.27,44.29 128.9,44.92 128.9,48.73 129.53,49.37 132.07,49.37 132.71,48.73 IC9.12
N$27
  Bottom 0.61: IC7.14 35.55,44.92 34.92,44.29 30.47,44.29 29.2,45.55 29.2,48.1 28.57,48.73 27.3,48.73 26.66,48.1 26.66,43.02 27.93,41.75 40,41.75 41.27,40.48 41.27,32.22 42.54,30.95 IC11.1
N$28
  Top 0.61: IC7.9 22.86,44.29 24.12,43.02 86.35,43.02 86.99,43.65 IC8.14
N$29
  Bottom 0.61: IC8.9 74.29,43.02 75.56,41.75 136.52,41.75 137.79,43.02 IC9.14
N$30
  Top 0.61: IC9.9 125.09,43.02 125.72,42.38 130.17,42.38 130.81,41.75 IC10.14
N$31
  Bottom 0.61: R1.1 6.98,74.77 IC1.16
N$32
  Bottom 0.61: R2.1 12.06,73.49 IC1.15
N$33
  Top 0.61: IC1.8 29.84,64.6 31.11,65.88 31.11,77.94 29.84,79.21 13.33,79.21 12.06,77.94 R3.1
N$34
  Bottom 0.61: R4.1 14.6,77.94 15.87,79.21 27.3,79.21 28.57,77.94 28.57,73.49 IC1.9
N$35
  Bottom 0.61: IC1.13 R5.1
N$36
  Bottom 0.61: R6.1 18.41,74.77 18.41,70.95 17.77,70.32 15.24,70.32 14.6,70.95 IC1.14
N$37
  Bottom 0.61: IC1.11 R7.1
N$38
  Bottom 0.61: IC1.10 R8.1
N$39
  Bottom 0.61: R9.1 26.66,76.03 26.03,75.4 26.03,68.41 25.39,67.78 10.16,67.78 9.52,67.14 IC1.1
N$40
  Top 0.61: IC1.2 12.06,67.14 12.7,67.78 28.57,67.78 29.84,69.05 R10.1
N$41
  Bottom 0.61: R11.1 32.38,74.77 IC2.16
N$42
  Bottom 0.61: R12.1 34.92,75.4 37.46,72.86 IC2.15
N$43
  Bottom 0.61: R13.1 37.46,77.94 38.73,79.21 54.61,79.21 56.51,77.3 56.51,65.88 55.24,64.6 IC2.8
N$44
  Bottom 0.61: R14.1 40,77.3 40.64,77.94 50.8,77.94 51.43,77.3 51.43,73.49 IC2.9
N$45
  Bottom 0.61: IC2.13 R15.1
N$46
  Bottom 0.61: R16.1 43.81,74.77 43.81,70.95 43.18,70.32 41.27,70.32 40,71.59 IC2.14
N$47
  Bottom 0.61: IC2.11 R17.1
N$48
  Bottom 0.61: IC2.10 R18.1
N$49
  Bottom 0.61: R19.1 52.7,75.4 53.97,74.13 53.97,69.05 52.7,67.78 36.19,67.78 34.92,66.51 IC2.1
N$50
  Bottom 0.61: R20.1 55.24,67.78 53.97,66.51 38.1,66.51 37.46,65.88 IC2.2
N$51
  Bottom 0.61: R21.1 60.32,73.49 IC3.16
N$52
  Bottom 0.61: R22.1 62.86,73.49 IC3.15
N$53
  Top 0.61: IC3.8 80.64,64.6 81.91,65.88 81.91,77.94 80.64,79.21 64.13,79.21 62.86,77.94 R23.1
N$54
  Bottom 0.61: IC3.9 78.1,72.86 76.83,74.13 76.83,77.94 75.56,79.21 66.67,79.21 65.4,77.94 R24.1
N$55
  Bottom 0.61: R25.1 IC3.13 67.94,71.59
N$56
  Bottom 0.61: R26.1 69.21,74.77 69.21,70.95 68.57,70.32 66.03,70.32 65.4,70.95 IC3.14
N$57
  Bottom 0.61: IC3.11 R27.1
N$58
  Bottom 0.61: IC3.10 R28.1
N$59
  Bottom 0.61: R29.1 79.37,74.77 79.37,68.41 78.73,67.78 61.59,67.78 60.32,66.51 IC3.1
N$60
  Top 0.61: IC3.2 62.86,66.51 64.13,67.78 79.37,67.78 80.64,69.05 R30.1
N$61
  Bottom 0.61: R31.1 85.72,73.49 IC4.16
N$62
  Bottom 0.61: R32.1 88.26,73.49 IC4.15
N$63
  Bottom 0.61: IC4.8 105.41,64.6 107.31,66.51 107.31,77.3 105.41,79.21 89.53,79.21 88.26,77.94 R33.1
N$64
  Bottom 0.61: R34.1 90.8,77.3 91.44,77.94 101.59,77.94 102.23,77.3 102.23,73.49 IC4.9
N$65
  Bottom 0.61: IC4.13 R35.1 93.34,76.67
N$66
  Bottom 0.61: R36.1 94.61,74.77 94.61,70.95 93.97,70.32 91.44,70.32 90.8,70.95 IC4.14
N$67
  Bottom 0.61: IC4.11 R37.1
N$68
  Bottom 0.61: IC4.10 R38.1
N$69
  Bottom 0.61: R39.1 103.5,75.4 104.77,74.13 104.77,69.05 103.5,67.78 86.99,67.78 85.72,66.51 IC4.1
N$70
  Bottom 0.61: R40.1 106.04,67.78 104.77,66.51 89.53,66.51 88.26,65.24 IC4.2
N$71
  Bottom 0.61: R41.1 111.12,73.49 IC5.16
N$72
  Bottom 0.61: R42.1 113.66,73.49 IC5.15
N$73
  Top 0.61: IC5.8 131.44,64.6 132.71,65.88 132.71,77.3 130.81,79.21 114.93,79.21 113.66,77.94 R43.1
N$74
  Bottom 0.61: R44.1 116.2,77.94 117.47,79.21 128.9,79.21 130.17,77.94 130.17,73.49 IC5.9
N$75
  Bottom 0.61: IC5.13 R45.1
N$76
  Bottom 0.61: R46.1 120.01,74.77 120.01,70.95 119.38,70.32 116.83,70.32 116.2,70.95 IC5.14
N$77
  Bottom 0.61: IC5.11 R47.1
N$78
  Bottom 0.61: IC5.10 R48.1
N$79
  Bottom 0.61: R49.1 127.63,74.77 127.63,69.05 126.36,67.78 112.39,67.78 111.12,66.51 IC5.1 111.12,63.97
N$80
  Top 0.61: IC5.2 113.66,66.51 114.93,67.78 130.17,67.78 131.44,69.05 R50.1
N$81
  Bottom 0.61: R51.1 136.52,73.49 IC6.16
N$82
  Bottom 0.61: R52.1 139.06,73.49 IC6.15
N$83
  Bottom 0.61: R53.1 139.06,77.94 140.97,79.84 156.84,79.84 158.75,77.94 158.75,66.51 156.84,64.6 IC6.8
N$84
  Bottom 0.61: R54.1 141.6,76.67 142.87,77.94 154.94,77.94 155.57,77.3 155.57,73.49 IC6.9
N$85
  Bottom 0.61: IC6.13 R55.1
N$86
  Bottom 0.61: IC6.14 141.6,70.95 142.23,70.32 144.78,70.32 145.41,70.95 145.41,74.77 R56.1
N$87
  Bottom 0.61: IC6.11 R57.1
N$88
  Bottom 0.61: IC6.10 R58.1
N$89
  Bottom 0.61: R59.1 153.03,74.77 153.03,69.05 151.76,67.78 137.79,67.78 136.52,66.51 IC6.1
N$90
  Bottom 0.61: R60.1 156.84,67.78 155.57,66.51 140.33,66.51 139.06,65.24 IC6.2
N$91
  Bottom 0.61: R1.2 SV1.1
N$92
  Bottom 0.61: R2.2 SV1.2
N$93
  Bottom 0.61: R3.2 SV1.3
N$94
  Bottom 0.61: R4.2 SV1.4
N$95
  Bottom 0.61: R5.2 SV1.5
N$96
  Bottom 0.61: R6.2 SV1.6
N$97
  Bottom 0.61: R7.2 SV1.7
N$98
  Bottom 0.61: R8.2 SV1.8
N$99
  Bottom 0.61: R9.2 SV1.9
N$100
  Bottom 0.61: R10.2 SV1.10
N$101
  Bottom 0.61: R11.2 SV2.1
N$102
  Bottom 0.61: R12.2 SV2.2
N$103
  Bottom 0.61: R13.2 SV2.3
N$104
  Bottom 0.61: R14.2 SV2.4
N$105
  Bottom 0.61: R15.2 SV2.5
N$106
  Bottom 0.61: R16.2 SV2.6
N$107
  Bottom 0.61: R17.2 SV2.7
N$108
  Bottom 0.61: R18.2 SV2.8
N$109
  Bottom 0.61: R19.2 SV2.9
N$110
  Bottom 0.61: R20.2 SV2.10
N$111
  Bottom 0.61: R21.2 SV3.1
N$112
  Bottom 0.61: R22.2 SV3.2
N$113
  Bottom 0.61: R23.2 SV3.3
N$114
  Bottom 0.61: R24.2 SV3.4
N$115
  Bottom 0.61: R25.2 SV3.5
N$116
  Bottom 0.61: R26.2 SV3.6
N$117
  Bottom 0.61: R27.2 SV3.7
N$118
  Bottom 0.61: R28.2 SV3.8
N$119
  Bottom 0.61: R29.2 SV3.9
N$120
  Bottom 0.61: R30.2 SV3.10
N$121
  Bottom 0.61: R31.2 SV4.1
N$122
  Bottom 0.61: R32.2 SV4.2
N$123
  Bottom 0.61: R33.2 SV4.3
N$124
  Bottom 0.61: R34.2 SV4.4
N$125
  Bottom 0.61: R35.2 SV4.5
N$126
  Bottom 0.61: R36.2 SV4.6
N$127
  Bottom 0.61: R37.2 SV4.7
N$128
  Bottom 0.61: R38.2 SV4.8
N$129
  Bottom 0.61: R39.2 SV4.9
N$130
  Bottom 0.61: R40.2 SV4.10
N$131
  Bottom 0.61: R41.2 SV5.1
N$132
  Bottom 0.61: R42.2 SV5.2
N$133
  Bottom 0.61: R43.2 SV5.3
N$134
  Bottom 0.61: R44.2 SV5.4
N$135
  Bottom 0.61: R45.2 SV5.5
N$136
  Bottom 0.61: R46.2 SV5.6
N$137
  Bottom 0.61: R47.2 SV5.7
N$138
  Bottom 0.61: R48.2 SV5.8
N$139
  Bottom 0.61: R49.2 SV5.9
N$140
  Bottom 0.61: R50.2 SV5.10
N$141
  Bottom 0.61: R51.2 SV6.1
N$142
  Bottom 0.61: R52.2 SV6.2
N$143
  Bottom 0.61: R53.2 SV6.3
N$144
  Bottom 0.61: R54.2 SV6.4
N$145
  Bottom 0.61: R55.2 SV6.5
N$146
  Bottom 0.61: R56.2 SV6.6
N$147
  Bottom 0.61: R57.2 SV6.7
N$148
  Bottom 0.61: R58.2 SV6.8
N$149
  Bottom 0.61: R59.2 SV6.9
N$150
  Bottom 0.61: R60.2 SV6.10
N$151
  Bottom 0.61: Q1.2 64.13,18.25 65.4,19.52 IC12.1
N$152
  Bottom 0.61: Q1.1 57.78,17.61 59.05,16.34 66.67,16.34 67.94,17.61 IC12.2
N$153
  Bottom 0.813: IC12.3 70.48,17.61 71.75,16.34 G1.+ 104.77,18.88
N$154
  Bottom 0.61: 73.02,31.58 IC13.2
  Bottom 0.813: IC12.5 73.02,31.58 71.11,33.49 R61.1 67.3,35.4 65.4,35.4 64.13,36.66 IC11.10
N$155
  Bottom 0.813: IC11.9 64.13,32.22 65.4,33.49 R62.1 66.67,32.22 67.94,30.95 69.21,30.95 70.48,29.68 IC12.6 70.48,26.5 71.75,25.23 75.56,25.23 76.83,26.5 76.83,27.14 77.46,27.78 IC13.4
N$156
  Bottom 0.813: R63.2 120.01,4.28 121.28,3.01 128.27,3.01 128.9,2.38 SV7.1
N$157
  Bottom 0.813: SV7.2 131.44,3.65 128.27,6.82 R64.2
N$158
  Bottom 0.813: R65.2 133.98,5.55 SV7.3
N$159
  Bottom 0.813: SV7.4 136.52,5.55 137.79,6.82 R66.2
N$160
  Bottom 0.813: SV7.5 139.06,4.28 141.6,6.82 R67.2
N$161
  Bottom 0.813: R68.2 147.31,6.82 145.41,4.92 142.87,4.92 141.6,3.65 SV7.6
N$162
  Bottom 0.813: SV7.7 147.31,4.92 154.94,4.92 R69.2
N$163
  Bottom 1.778: X1.1 D1.A
N$164  (2 unrouted)
  Bottom 1.778: IC14.IN 43.18,22.06 41.91,23.33 31.74,23.33 28.57,26.5 C14.+ 26.03,28.41 D1.C 12.7,28.41 11.43,29.68 11.43,34.12
N$165
  Bottom 0.813: IC11.11 61.59,39.21 64.13,41.75 JP3.1
N$166
  Top 0.61: SV8.3 76.83,36.66 76.19,36.03 59.69,36.03 59.05,36.66 IC11.12
  Bottom 0.813: IC11.12 59.05,39.84 60.96,41.75 JP2.1
N$167
  Top 0.61: SV8.4 79.37,36.03 78.1,34.76 57.78,34.76 56.51,36.03 IC11.13
  Bottom 0.813: IC11.13 56.51,40.48 57.78,41.75 JP1.1
N$168
  Bottom 0.813: T1.B R70.2
N$169
  Bottom 0.813: T2.B R71.2
N$170
  Bottom 0.813: T3.B R72.2
N$171
  Bottom 0.813: T4.B R73.2
N$172
  Bottom 0.813: T5.B R74.2
N$173
  Bottom 0.813: T6.B R75.2
N$174
  Bottom 0.813: T7.B R76.2
N$175
  Bottom 0.813: T1.C 119.38,16.98 120.01,16.34 R63.1
N$176
  Bottom 0.813: T2.C 125.09,16.98 126.36,15.71 R64.1
N$177
  Bottom 0.813: T3.C 131.44,16.98 132.71,15.71 R65.1
N$178
  Bottom 0.813: T4.C 137.16,16.98 138.42,15.71 R66.1
N$179
  Bottom 0.813: T5.C 143.5,16.98 144.78,15.71 R67.1
N$180
  Bottom 0.813: T6.C 149.85,16.98 151.12,15.71 R68.1
N$181
  Bottom 0.813: T7.C 155.57,16.98 156.84,15.71 R69.1
N$182
  Bottom 0.61: R70.1 120.01,33.49 121.28,34.76 126.99,34.76 128.27,36.03 IC10.15
N$183
  Bottom 0.61: R71.1 126.36,29.04 125.72,29.68 IC10.1
N$184
  Bottom 0.61: IC10.2 128.27,29.68 130.81,27.14 R72.1
N$185
  Bottom 0.61: IC10.3 130.81,29.68 132.07,28.41 137.79,28.41 R73.1
N$186
  Bottom 0.61: IC10.4 133.34,30.32 133.98,29.68 142.87,29.68 R74.1
N$187
  Bottom 0.61: IC10.5 135.88,33.49 137.79,35.4 145.41,35.4 147.95,32.86 147.95,27.78 148.59,27.14 R75.1
N$188
  Bottom 0.61: IC10.6 138.42,33.49 139.06,34.12 144.78,34.12 146.68,32.22 146.68,27.14 147.95,25.87 155.57,25.87 R76.1
N$189
  Top 0.61: SV8.5 81.91,36.66 78.73,33.49 71.11,33.49 69.84,32.22 65.4,32.22 64.13,33.49 52.07,33.49 51.43,32.86 IC11.4
  Bottom 0.61: R77.2 IC11.4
